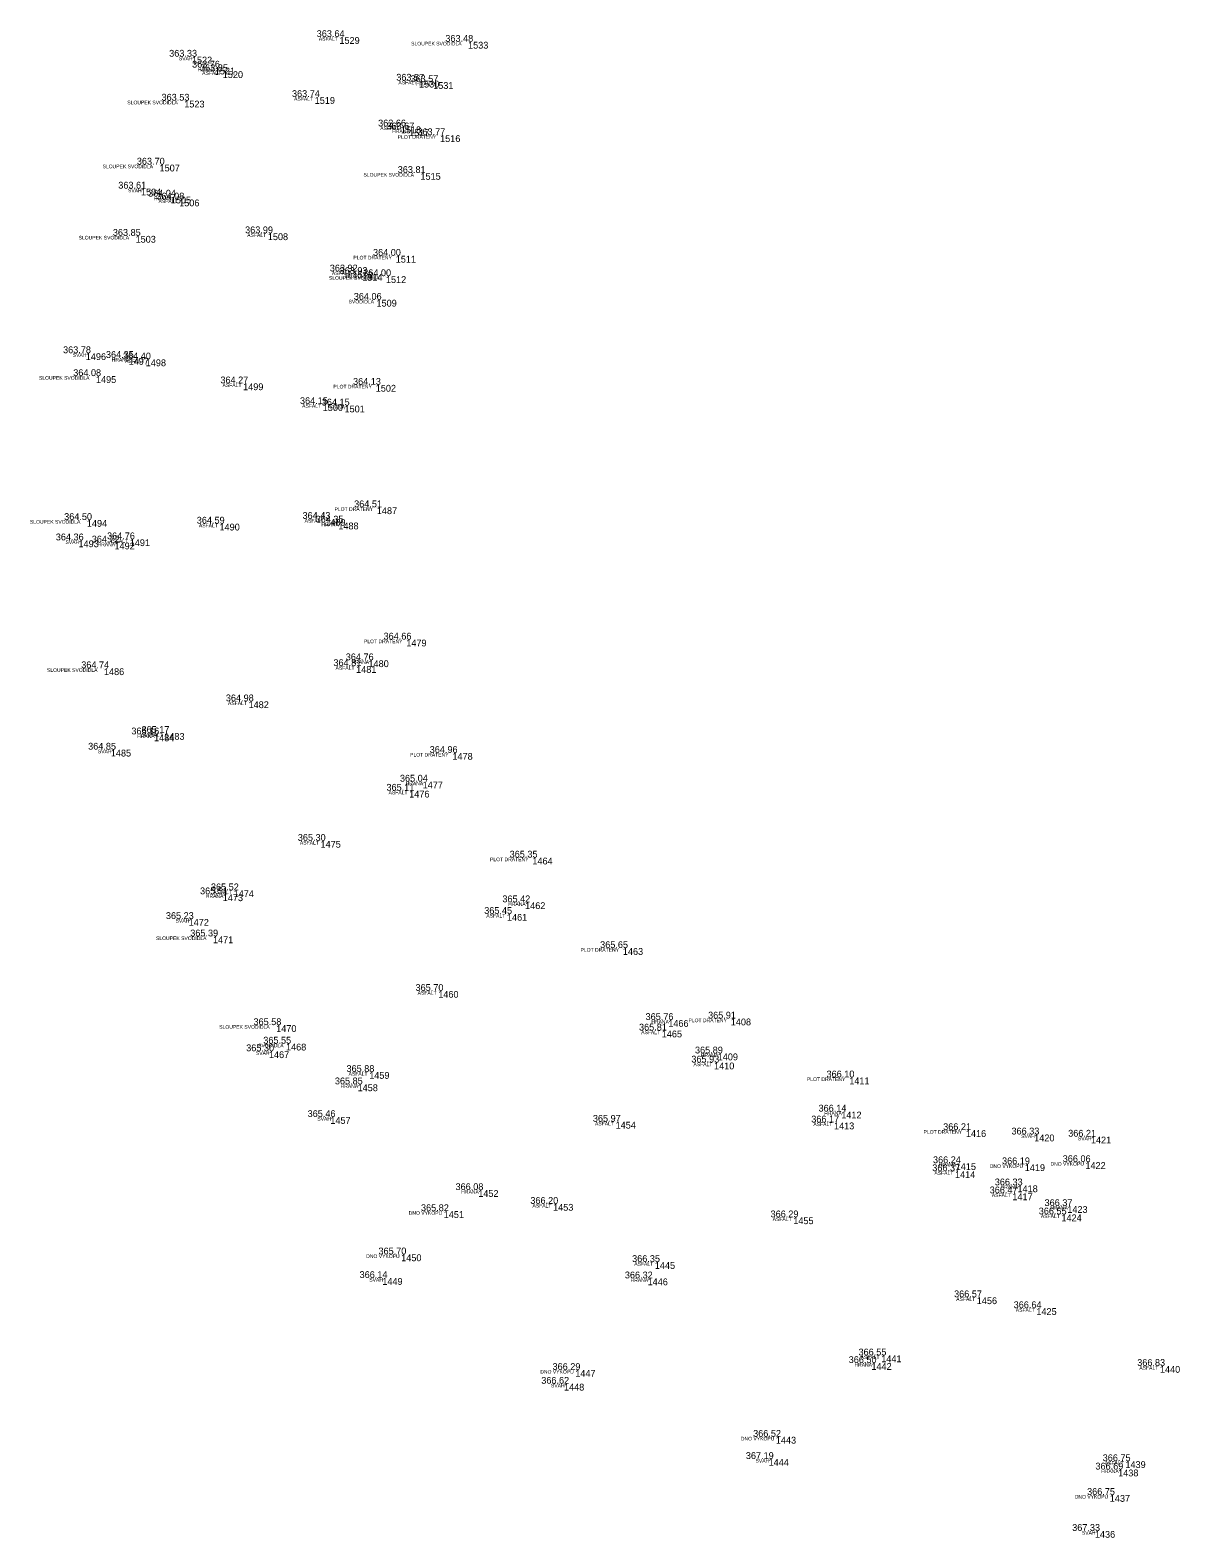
# Model space of a CAD drawing. Extents: x -597865 to -597551, y -1151663 to -1149883.
# Drawn here: x -597683.47 to -597651.83, y -1150425.73 to -1150384.24 of the extents above; entities that cross this region are included whole.
import ezdxf

# ---------------------------------------------------------------- set-up
doc = ezdxf.new("R2010")
doc.units = 0
for name, color, linetype in [('Vrstva 11', 7, 'Continuous'), ('Vrstva 12', 7, 'Continuous'), ('Vrstva 13', 7, 'Continuous'), ('Vrstva 14', 7, 'Continuous')]:
    doc.layers.add(name, color=color, linetype=linetype)

msp = doc.modelspace()

# ---------------------------------------------------------------- linework, layer by layer
at = {"layer": 'Vrstva 11'}
for p, q in [((-597674.96, -1150384.43), (-597674.96, -1150384.43)), ((-597671.42, -1150384.56), (-597671.42, -1150384.56)), ((-597679.02, -1150384.97), (-597679.02, -1150384.97)), ((-597678.39, -1150385.27), (-597678.39, -1150385.27)), ((-597678.17, -1150385.37), (-597678.17, -1150385.37)), ((-597672.77, -1150385.63), (-597672.77, -1150385.63)), ((-597672.38, -1150385.67), (-597672.38, -1150385.67)), ((-597679.23, -1150386.18), (-597679.23, -1150386.18)), ((-597675.64, -1150386.08), (-597675.64, -1150386.08)), ((-597673.27, -1150386.89), (-597673.27, -1150386.89)), ((-597673.04, -1150386.97), (-597673.04, -1150386.97)), ((-597672.19, -1150387.13), (-597672.19, -1150387.13)), ((-597679.91, -1150387.94), (-597679.91, -1150387.94)), ((-597672.73, -1150388.17), (-597672.73, -1150388.17)), ((-597680.42, -1150388.6), (-597680.42, -1150388.6)), ((-597679.6, -1150388.82), (-597679.6, -1150388.82)), ((-597679.37, -1150388.9), (-597679.37, -1150388.9)), ((-597680.57, -1150389.9), (-597680.57, -1150389.9)), ((-597676.93, -1150389.83), (-597676.93, -1150389.83)), ((-597673.41, -1150390.45), (-597673.41, -1150390.45)), ((-597674.6, -1150390.88), (-597674.6, -1150390.88)), ((-597674.33, -1150390.95), (-597674.33, -1150390.95)), ((-597673.68, -1150391.01), (-597673.68, -1150391.01)), ((-597673.94, -1150391.66), (-597673.94, -1150391.66)), ((-597681.94, -1150393.13), (-597681.94, -1150393.13)), ((-597680.76, -1150393.26), (-597680.76, -1150393.26)), ((-597680.29, -1150393.3), (-597680.29, -1150393.3)), ((-597681.66, -1150393.76), (-597681.66, -1150393.76)), ((-597677.61, -1150393.96), (-597677.61, -1150393.96)), ((-597673.96, -1150394), (-597673.96, -1150394)), ((-597675.42, -1150394.53), (-597675.42, -1150394.53)), ((-597674.82, -1150394.57), (-597674.82, -1150394.57)), ((-597673.93, -1150397.37), (-597673.93, -1150397.37)), ((-597681.91, -1150397.72), (-597681.91, -1150397.72)), ((-597678.26, -1150397.82), (-597678.26, -1150397.82)), ((-597675.35, -1150397.69), (-597675.35, -1150397.69)), ((-597674.99, -1150397.79), (-597674.99, -1150397.79)), ((-597682.14, -1150398.28), (-597682.14, -1150398.28)), ((-597681.15, -1150398.34), (-597681.15, -1150398.34)), ((-597680.73, -1150398.25), (-597680.73, -1150398.25)), ((-597673.12, -1150401.01), (-597673.12, -1150401.01)), ((-597674.16, -1150401.58), (-597674.16, -1150401.58)), ((-597681.44, -1150401.8), (-597681.44, -1150401.8)), ((-597674.5, -1150401.74), (-597674.5, -1150401.74)), ((-597677.46, -1150402.71), (-597677.46, -1150402.71)), ((-597680.06, -1150403.62), (-597680.06, -1150403.62)), ((-597679.78, -1150403.58), (-597679.78, -1150403.58)), ((-597681.25, -1150404.04), (-597681.25, -1150404.04)), ((-597671.85, -1150404.13), (-597671.85, -1150404.13)), ((-597672.67, -1150404.92), (-597672.67, -1150404.92)), ((-597673.04, -1150405.17), (-597673.04, -1150405.17)), ((-597675.48, -1150406.55), (-597675.48, -1150406.55)), ((-597669.65, -1150407.01), (-597669.65, -1150407.01)), ((-597677.87, -1150407.91), (-597677.87, -1150407.91)), ((-597678.17, -1150408.02), (-597678.17, -1150408.02)), ((-597669.85, -1150408.24), (-597669.85, -1150408.24)), ((-597679.11, -1150408.7), (-597679.11, -1150408.7)), ((-597670.35, -1150408.56), (-597670.35, -1150408.56)), ((-597678.44, -1150409.18), (-597678.44, -1150409.18)), ((-597667.16, -1150409.5), (-597667.16, -1150409.5)), ((-597672.24, -1150410.68), (-597672.24, -1150410.68)), ((-597676.7, -1150411.62), (-597676.7, -1150411.62)), ((-597665.91, -1150411.48), (-597665.91, -1150411.48)), ((-597664.19, -1150411.44), (-597664.19, -1150411.44)), ((-597666.09, -1150411.77), (-597666.09, -1150411.77)), ((-597676.9, -1150412.34), (-597676.9, -1150412.34)), ((-597676.43, -1150412.13), (-597676.43, -1150412.13)), ((-597664.55, -1150412.4), (-597664.55, -1150412.4)), ((-597674.14, -1150412.91), (-597674.14, -1150412.91)), ((-597664.65, -1150412.65), (-597664.65, -1150412.65)), ((-597674.46, -1150413.25), (-597674.46, -1150413.25)), ((-597660.93, -1150413.06), (-597660.93, -1150413.06)), ((-597675.21, -1150414.15), (-597675.21, -1150414.15)), ((-597661.15, -1150414), (-597661.15, -1150414)), ((-597667.36, -1150414.28), (-597667.36, -1150414.28)), ((-597661.35, -1150414.3), (-597661.35, -1150414.3)), ((-597657.72, -1150414.51), (-597657.72, -1150414.51)), ((-597655.84, -1150414.63), (-597655.84, -1150414.63)), ((-597654.28, -1150414.69), (-597654.28, -1150414.69)), ((-597654.43, -1150415.39), (-597654.43, -1150415.39)), ((-597658.02, -1150415.64), (-597658.02, -1150415.64)), ((-597658, -1150415.42), (-597658, -1150415.42)), ((-597656.1, -1150415.45), (-597656.1, -1150415.45)), ((-597671.14, -1150416.16), (-597671.14, -1150416.16)), ((-597656.3, -1150416.03), (-597656.3, -1150416.03)), ((-597669.08, -1150416.54), (-597669.08, -1150416.54)), ((-597656.44, -1150416.25), (-597656.44, -1150416.25)), ((-597654.93, -1150416.6), (-597654.93, -1150416.6)), ((-597672.09, -1150416.74), (-597672.09, -1150416.74)), ((-597662.47, -1150416.91), (-597662.47, -1150416.91)), ((-597655.09, -1150416.83), (-597655.09, -1150416.83)), ((-597673.26, -1150417.93), (-597673.26, -1150417.93)), ((-597666.28, -1150418.14), (-597666.28, -1150418.14)), ((-597673.78, -1150418.58), (-597673.78, -1150418.58)), ((-597666.48, -1150418.59), (-597666.48, -1150418.59)), ((-597657.42, -1150419.11), (-597657.42, -1150419.11)), ((-597655.78, -1150419.41), (-597655.78, -1150419.41)), ((-597660.05, -1150420.71), (-597660.05, -1150420.71)), ((-597668.47, -1150421.11), (-597668.47, -1150421.11)), ((-597660.32, -1150420.92), (-597660.32, -1150420.92)), ((-597652.38, -1150421), (-597652.38, -1150421)), ((-597668.78, -1150421.49), (-597668.78, -1150421.49)), ((-597662.95, -1150422.95), (-597662.95, -1150422.95)), ((-597663.15, -1150423.56), (-597663.15, -1150423.56)), ((-597653.33, -1150423.62), (-597653.33, -1150423.62)), ((-597653.53, -1150423.85), (-597653.53, -1150423.85)), ((-597653.76, -1150424.55), (-597653.76, -1150424.55)), ((-597654.17, -1150425.54), (-597654.17, -1150425.54))]:
    msp.add_line(p, q, dxfattribs=at)

# ---------------------------------------------------------------- texts
at = {"layer": 'Vrstva 12'}
for s, p in [('363.64 ', (-597675.585, -1150384.43)), ('363.48 ', (-597672.045, -1150384.56)), ('363.33 ', (-597679.645, -1150384.97)), ('363.76 ', (-597679.015, -1150385.27)), ('363.85 ', (-597678.795, -1150385.37)), ('363.57 ', (-597673.395, -1150385.63)), ('363.57 ', (-597673.005, -1150385.67)), ('363.74 ', (-597676.265, -1150386.08)), ('363.53 ', (-597679.855, -1150386.18)), ('363.66 ', (-597673.895, -1150386.89)), ('363.67 ', (-597673.665, -1150386.97)), ('363.77 ', (-597672.815, -1150387.13)), ('363.70 ', (-597680.535, -1150387.94)), ('363.81 ', (-597673.355, -1150388.17)), ('363.61 ', (-597681.045, -1150388.6)), ('364.04 ', (-597680.225, -1150388.82)), ('364.08 ', (-597679.995, -1150388.9)), ('363.99 ', (-597677.555, -1150389.83)), ('363.85 ', (-597681.195, -1150389.9)), ('364.00 ', (-597674.035, -1150390.45)), ('363.92 ', (-597675.225, -1150390.88)), ('363.93 ', (-597674.955, -1150390.95)), ('364.00 ', (-597674.305, -1150391.01)), ('364.06 ', (-597674.565, -1150391.66)), ('363.78 ', (-597682.565, -1150393.13)), ('364.35 ', (-597681.385, -1150393.26)), ('364.40 ', (-597680.915, -1150393.3)), ('364.08 ', (-597682.285, -1150393.76)), ('364.27 ', (-597678.235, -1150393.96)), ('364.13 ', (-597674.585, -1150394)), ('364.15 ', (-597676.045, -1150394.53)), ('364.15 ', (-597675.445, -1150394.57)), ('364.50 ', (-597682.535, -1150397.72)), ('364.43 ', (-597675.975, -1150397.69)), ('364.51 ', (-597674.555, -1150397.37)), ('364.59 ', (-597678.885, -1150397.82)), ('364.35 ', (-597675.615, -1150397.79)), ('364.36 ', (-597682.765, -1150398.28)), ('364.72 ', (-597681.775, -1150398.34)), ('364.76 ', (-597681.355, -1150398.25)), ('364.66 ', (-597673.745, -1150401.01)), ('364.74 ', (-597682.065, -1150401.8)), ('364.81 ', (-597675.125, -1150401.74)), ('364.76 ', (-597674.785, -1150401.58)), ('364.98 ', (-597678.085, -1150402.71)), ('365.16 ', (-597680.685, -1150403.62)), ('365.17 ', (-597680.405, -1150403.58)), ('364.85 ', (-597681.875, -1150404.04)), ('364.96 ', (-597672.475, -1150404.13)), ('365.11 ', (-597673.665, -1150405.17)), ('365.04 ', (-597673.295, -1150404.92)), ('365.30 ', (-597676.105, -1150406.55)), ('365.35 ', (-597670.275, -1150407.01)), ('365.51 ', (-597678.795, -1150408.02)), ('365.52 ', (-597678.495, -1150407.91)), ('365.42 ', (-597670.475, -1150408.24)), ('365.23 ', (-597679.735, -1150408.7)), ('365.45 ', (-597670.975, -1150408.56)), ('365.39 ', (-597679.065, -1150409.18)), ('365.65 ', (-597667.785, -1150409.5)), ('365.70 ', (-597672.865, -1150410.68)), ('365.91 ', (-597664.815, -1150411.44)), ('365.58 ', (-597677.325, -1150411.62)), ('365.81 ', (-597666.715, -1150411.77)), ('365.76 ', (-597666.535, -1150411.48)), ('365.55 ', (-597677.055, -1150412.13)), ('365.30 ', (-597677.525, -1150412.34)), ('365.93 ', (-597665.275, -1150412.65)), ('365.89 ', (-597665.175, -1150412.4)), ('365.88 ', (-597674.765, -1150412.91)), ('366.10 ', (-597661.555, -1150413.06)), ('365.85 ', (-597675.085, -1150413.25)), ('365.46 ', (-597675.835, -1150414.15)), ('365.97 ', (-597667.985, -1150414.28)), ('366.17 ', (-597661.975, -1150414.3)), ('366.14 ', (-597661.775, -1150414)), ('366.21 ', (-597658.345, -1150414.51)), ('366.33 ', (-597656.465, -1150414.63)), ('366.21 ', (-597654.905, -1150414.69)), ('366.24 ', (-597658.625, -1150415.42)), ('366.19 ', (-597656.725, -1150415.45)), ('366.06 ', (-597655.055, -1150415.39)), ('366.37 ', (-597658.645, -1150415.64)), ('366.08 ', (-597671.765, -1150416.16)), ('366.47 ', (-597657.065, -1150416.25)), ('366.33 ', (-597656.925, -1150416.03)), ('365.82 ', (-597672.715, -1150416.74)), ('366.20 ', (-597669.705, -1150416.54)), ('366.55 ', (-597655.715, -1150416.83)), ('366.37 ', (-597655.555, -1150416.6)), ('366.29 ', (-597663.095, -1150416.91)), ('365.70 ', (-597673.885, -1150417.93)), ('366.35 ', (-597666.905, -1150418.14)), ('366.14 ', (-597674.405, -1150418.58)), ('366.32 ', (-597667.105, -1150418.59)), ('366.57 ', (-597658.045, -1150419.11)), ('366.64 ', (-597656.405, -1150419.41)), ('366.50 ', (-597660.945, -1150420.92)), ('366.55 ', (-597660.675, -1150420.71)), ('366.83 ', (-597653.005, -1150421)), ('366.29 ', (-597669.095, -1150421.11)), ('366.62 ', (-597669.405, -1150421.49)), ('366.52 ', (-597663.575, -1150422.95)), ('367.19 ', (-597663.775, -1150423.56)), ('366.69 ', (-597654.155, -1150423.85)), ('366.75 ', (-597653.955, -1150423.62)), ('366.75 ', (-597654.385, -1150424.55)), ('367.33 ', (-597654.795, -1150425.54))]:
    msp.add_text(s, height=0.1875, dxfattribs=at).set_placement(p)
at = {"layer": 'Vrstva 13'}
for s, p in [('1529', (-597674.96, -1150384.617)), ('1533', (-597671.42, -1150384.748)), ('1522', (-597679.02, -1150385.157)), ('1521', (-597678.39, -1150385.458)), ('1520', (-597678.17, -1150385.558)), ('1530', (-597672.77, -1150385.818)), ('1531', (-597672.38, -1150385.857)), ('1523', (-597679.23, -1150386.367)), ('1519', (-597675.64, -1150386.268)), ('1518', (-597673.27, -1150387.078)), ('1517', (-597673.04, -1150387.157)), ('1516', (-597672.19, -1150387.318)), ('1507', (-597679.91, -1150388.127)), ('1515', (-597672.73, -1150388.357)), ('1504', (-597680.42, -1150388.788)), ('1505', (-597679.6, -1150389.008)), ('1506', (-597679.37, -1150389.088)), ('1503', (-597680.57, -1150390.088)), ('1508', (-597676.93, -1150390.018)), ('1511', (-597673.41, -1150390.637)), ('1513', (-597674.6, -1150391.068)), ('1514', (-597674.33, -1150391.137)), ('1512', (-597673.68, -1150391.198)), ('1509', (-597673.94, -1150391.847)), ('1496', (-597681.94, -1150393.318)), ('1497', (-597680.76, -1150393.448)), ('1498', (-597680.29, -1150393.488)), ('1495', (-597681.66, -1150393.948)), ('1499', (-597677.61, -1150394.147)), ('1502', (-597673.96, -1150394.188)), ('1500', (-597675.42, -1150394.718)), ('1501', (-597674.82, -1150394.758)), ('1487', (-597673.93, -1150397.558)), ('1494', (-597681.91, -1150397.907)), ('1490', (-597678.26, -1150398.008)), ('1489', (-597675.35, -1150397.877)), ('1488', (-597674.99, -1150397.978)), ('1493', (-597682.14, -1150398.468)), ('1492', (-597681.15, -1150398.528)), ('1491', (-597680.73, -1150398.438)), ('1479', (-597673.12, -1150401.198)), ('1480', (-597674.16, -1150401.768)), ('1486', (-597681.44, -1150401.988)), ('1481', (-597674.5, -1150401.927)), ('1482', (-597677.46, -1150402.897)), ('1484', (-597680.06, -1150403.808)), ('1483', (-597679.78, -1150403.768)), ('1485', (-597681.25, -1150404.228)), ('1478', (-597671.85, -1150404.318)), ('1477', (-597672.67, -1150405.107)), ('1476', (-597673.04, -1150405.357)), ('1475', (-597675.48, -1150406.738)), ('1464', (-597669.65, -1150407.198)), ('1474', (-597677.87, -1150408.097)), ('1473', (-597678.17, -1150408.208)), ('1462', (-597669.85, -1150408.427)), ('1472', (-597679.11, -1150408.887)), ('1461', (-597670.35, -1150408.748)), ('1471', (-597678.44, -1150409.367)), ('1463', (-597667.16, -1150409.688)), ('1460', (-597672.24, -1150410.867)), ('1470', (-597676.7, -1150411.808)), ('1466', (-597665.91, -1150411.667)), ('1408', (-597664.19, -1150411.627)), ('1465', (-597666.09, -1150411.958)), ('1467', (-597676.9, -1150412.528)), ('1468', (-597676.43, -1150412.318)), ('1409', (-597664.55, -1150412.588)), ('1459', (-597674.14, -1150413.097)), ('1410', (-597664.65, -1150412.838)), ('1458', (-597674.46, -1150413.438)), ('1411', (-597660.93, -1150413.248)), ('1457', (-597675.21, -1150414.338)), ('1412', (-597661.15, -1150414.188)), ('1454', (-597667.36, -1150414.468)), ('1413', (-597661.35, -1150414.488)), ('1416', (-597657.72, -1150414.698)), ('1420', (-597655.84, -1150414.818)), ('1421', (-597654.28, -1150414.877)), ('1422', (-597654.43, -1150415.578)), ('1414', (-597658.02, -1150415.828)), ('1415', (-597658, -1150415.607)), ('1419', (-597656.1, -1150415.637)), ('1452', (-597671.14, -1150416.347)), ('1418', (-597656.3, -1150416.218)), ('1453', (-597669.08, -1150416.728)), ('1417', (-597656.44, -1150416.438)), ('1423', (-597654.93, -1150416.788)), ('1451', (-597672.09, -1150416.927)), ('1455', (-597662.47, -1150417.097)), ('1424', (-597655.09, -1150417.018)), ('1450', (-597673.26, -1150418.117)), ('1445', (-597666.28, -1150418.328)), ('1449', (-597673.78, -1150418.768)), ('1446', (-597666.48, -1150418.778)), ('1456', (-597657.42, -1150419.298)), ('1425', (-597655.78, -1150419.597)), ('1441', (-597660.05, -1150420.897)), ('1447', (-597668.47, -1150421.298)), ('1442', (-597660.32, -1150421.107)), ('1440', (-597652.38, -1150421.188)), ('1448', (-597668.78, -1150421.677)), ('1443', (-597662.95, -1150423.137)), ('1444', (-597663.15, -1150423.748)), ('1439', (-597653.33, -1150423.808)), ('1438', (-597653.53, -1150424.038)), ('1437', (-597653.76, -1150424.738)), ('1436', (-597654.17, -1150425.728))]:
    msp.add_text(s, height=0.1875, dxfattribs=at).set_placement(p)
at = {"layer": 'Vrstva 14'}
for s, p in [('ASFALT', (-597675.527, -1150384.53)), ('SLOUPEK SVODIDLA', (-597672.987, -1150384.66)), ('SVAH', (-597679.378, -1150385.07)), ('HRANA', (-597678.857, -1150385.37)), ('ASFALT', (-597678.737, -1150385.47)), ('ASFALT', (-597673.337, -1150385.73)), ('HRANA', (-597672.847, -1150385.77)), ('SLOUPEK SVODIDLA', (-597680.797, -1150386.28)), ('ASFALT', (-597676.207, -1150386.18)), ('ASFALT', (-597673.837, -1150386.99)), ('HRANA', (-597673.507, -1150387.07)), ('PLOT DRATENY', (-597673.355, -1150387.23)), ('SLOUPEK SVODIDLA', (-597681.477, -1150388.04)), ('SLOUPEK SVODIDLA', (-597674.297, -1150388.27)), ('SVAH', (-597680.778, -1150388.7)), ('HRANA', (-597680.067, -1150388.92)), ('ASFALT', (-597679.937, -1150389)), ('SLOUPEK SVODIDLA', (-597682.137, -1150390)), ('ASFALT', (-597677.497, -1150389.93)), ('PLOT DRATENY', (-597674.575, -1150390.55)), ('ASFALT', (-597675.167, -1150390.98)), ('SLOUPEK SVODIDLA', (-597675.247, -1150391.11)), ('HRANA', (-597674.797, -1150391.05)), ('SVODIDLA', (-597674.707, -1150391.76)), ('SVAH', (-597682.298, -1150393.23)), ('HRANA', (-597681.227, -1150393.36)), ('ASFALT', (-597680.857, -1150393.4)), ('SLOUPEK SVODIDLA', (-597683.227, -1150393.86)), ('ASFALT', (-597678.177, -1150394.06)), ('PLOT DRATENY', (-597675.125, -1150394.1)), ('ASFALT', (-597675.987, -1150394.63)), ('HRANA', (-597675.287, -1150394.67)), ('PLOT DRATENY', (-597675.095, -1150397.47)), ('SLOUPEK SVODIDLA', (-597683.477, -1150397.82)), ('ASFALT', (-597678.827, -1150397.92)), ('ASFALT', (-597675.917, -1150397.79)), ('HRANA', (-597675.457, -1150397.89)), ('SVAH', (-597682.498, -1150398.38)), ('HRANA', (-597681.617, -1150398.44)), ('ASFALT', (-597681.297, -1150398.35)), ('PLOT DRATENY', (-597674.285, -1150401.11)), ('HRANA', (-597674.627, -1150401.68)), ('SLOUPEK SVODIDLA', (-597683.007, -1150401.9)), ('ASFALT', (-597675.067, -1150401.84)), ('ASFALT', (-597678.027, -1150402.81)), ('HRANA', (-597680.527, -1150403.72)), ('ASFALT', (-597680.347, -1150403.68)), ('SVAH', (-597681.608, -1150404.14)), ('PLOT DRATENY', (-597673.015, -1150404.23)), ('HRANA', (-597673.137, -1150405.02)), ('ASFALT', (-597673.607, -1150405.27)), ('ASFALT', (-597676.047, -1150406.65)), ('PLOT DRATENY', (-597670.815, -1150407.11)), ('ASFALT', (-597678.437, -1150408.01)), ('HRANA', (-597678.637, -1150408.12)), ('HRANA', (-597670.317, -1150408.34)), ('SVAH', (-597679.468, -1150408.8)), ('ASFALT', (-597670.917, -1150408.66)), ('SLOUPEK SVODIDLA', (-597680.007, -1150409.28)), ('PLOT DRATENY', (-597668.325, -1150409.6)), ('ASFALT', (-597672.807, -1150410.78)), ('SLOUPEK SVODIDLA', (-597678.267, -1150411.72)), ('HRANA', (-597666.377, -1150411.58)), ('PLOT DRATENY', (-597665.355, -1150411.54)), ('ASFALT', (-597666.657, -1150411.87)), ('SVAH', (-597677.258, -1150412.44)), ('SVODIDLA', (-597677.197, -1150412.23)), ('HRANA', (-597665.017, -1150412.5)), ('ASFALT', (-597674.707, -1150413.01)), ('ASFALT', (-597665.217, -1150412.75)), ('HRANA', (-597674.927, -1150413.35)), ('PLOT DRATENY', (-597662.095, -1150413.16)), ('SVAH', (-597675.568, -1150414.25)), ('HRANA', (-597661.617, -1150414.1)), ('ASFALT', (-597667.927, -1150414.38)), ('ASFALT', (-597661.917, -1150414.4)), ('PLOT DRATENY', (-597658.885, -1150414.61)), ('SVAH', (-597656.198, -1150414.73)), ('SVAH', (-597654.638, -1150414.79)), ('DNO VYKOPU', (-597655.392, -1150415.49)), ('ASFALT', (-597658.587, -1150415.74)), ('HRANA', (-597658.467, -1150415.52)), ('DNO VYKOPU', (-597657.062, -1150415.55)), ('HRANA', (-597671.607, -1150416.26)), ('HRANA', (-597656.767, -1150416.13)), ('ASFALT', (-597669.647, -1150416.64)), ('ASFALT', (-597657.007, -1150416.35)), ('HRANA', (-597655.397, -1150416.7)), ('DNO VYKOPU', (-597673.052, -1150416.84)), ('ASFALT', (-597663.037, -1150417.01)), ('ASFALT', (-597655.657, -1150416.93)), ('DNO VYKOPU', (-597674.223, -1150418.03)), ('ASFALT', (-597666.847, -1150418.24)), ('SVAH', (-597674.138, -1150418.68)), ('HRANA', (-597666.947, -1150418.69)), ('ASFALT', (-597657.987, -1150419.21)), ('ASFALT', (-597656.347, -1150419.51)), ('ASFALT', (-597660.617, -1150420.81)), ('DNO VYKOPU', (-597669.432, -1150421.21)), ('HRANA', (-597660.787, -1150421.02)), ('ASFALT', (-597652.947, -1150421.1)), ('SVAH', (-597669.138, -1150421.59)), ('DNO VYKOPU', (-597663.912, -1150423.05)), ('SVAH', (-597663.508, -1150423.66)), ('ASFALT', (-597653.897, -1150423.72)), ('HRANA', (-597653.997, -1150423.95)), ('DNO VYKOPU', (-597654.723, -1150424.65)), ('SVAH', (-597654.528, -1150425.64))]:
    msp.add_text(s, height=0.1, dxfattribs=at).set_placement(p)

doc.saveas('drawing.dxf')
